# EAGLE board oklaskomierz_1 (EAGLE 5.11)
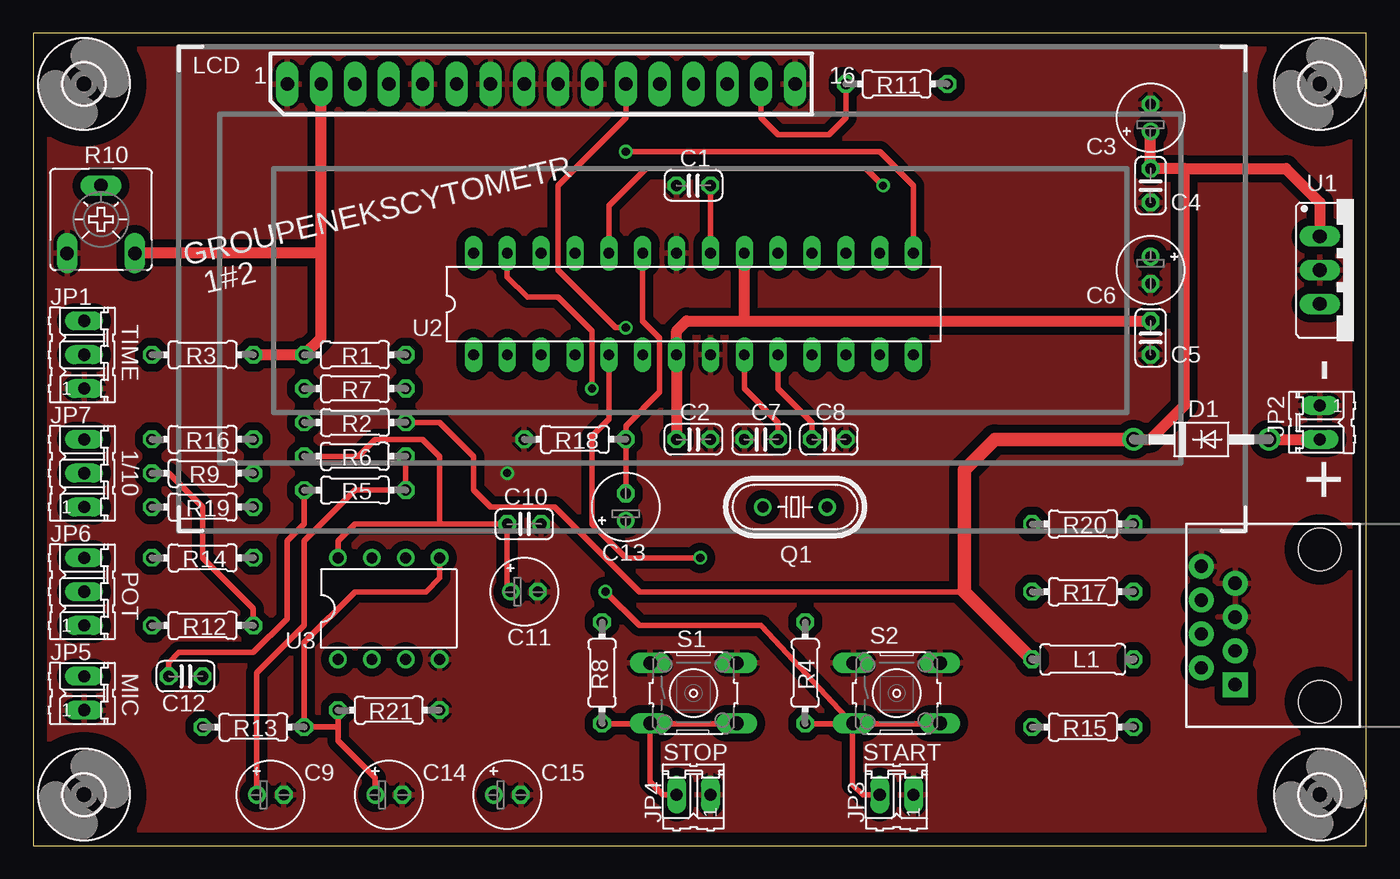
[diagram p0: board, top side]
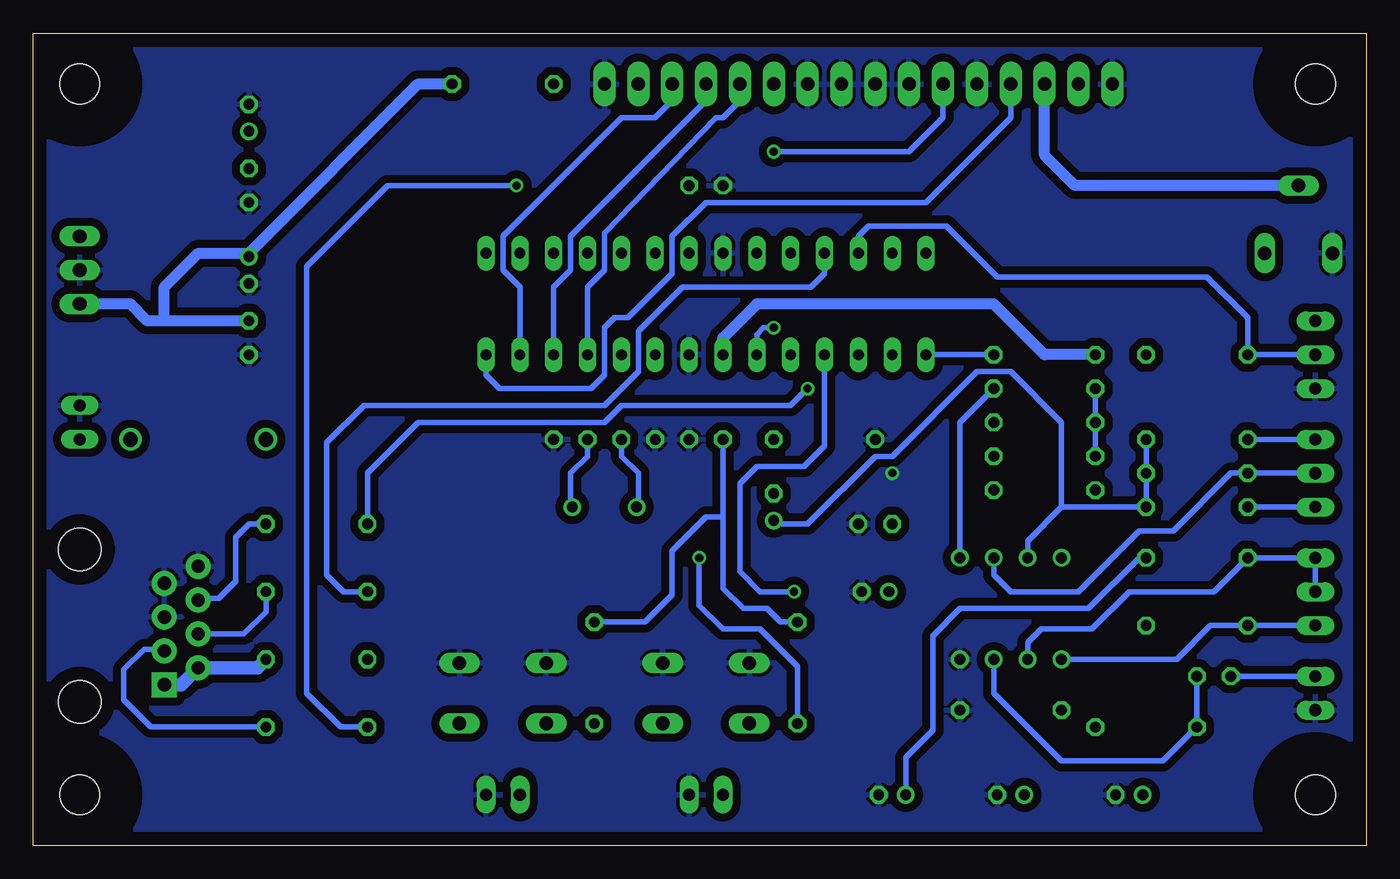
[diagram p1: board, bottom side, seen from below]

Size 100 x 60.95 mm. Coordinates in mm from the lower left corner, seen from the top.
Outline: 0,0 100,0 100,60.95 0,60.95 0,0
Copper layers (1*16): Top 0.035mm / dielectric 1.5mm / Bottom 0.035mm
Design rules "default *": minimum track width 16mil, minimum drill 24mil, track to track 8mil, track to pad 8mil, pad to pad 8mil, via to via 8mil, smd to smd 8mil, copper to edge 40mil, drill to drill 8mil, minimum pad ring 10mil, minimum via ring 8mil, stop-mask expansion 4mil, vias tented up to drill 0mil, thermal gap 10mil

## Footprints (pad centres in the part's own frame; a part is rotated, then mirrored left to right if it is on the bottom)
C025-024X044 = drill 0.813 octagon: 1 -1.27,0; 2 1.27,0
E2-5 = drill 0.813 pad 1.27 round: + -1.016,0 | drill 0.813 pad 1.27 octagon: - 1.016,0
RJ45-8 = drill 1 pad 1.88 square: 1 -4.445,6.35 | drill 1 pad 1.88 round: 2 -3.175,8.89; 3 -1.905,6.35; 4 -0.635,8.89; 5 0.635,6.35; 6 1.905,8.89; 7 3.175,6.35; 8 4.445,8.89 | hole 3.2: -5.715,0; 5.715,0
DO41-10 = drill 1.118 round: A 5.08,0; C -5.08,0
3,0 = hole 3: 0,0
03P = drill 0.914 long: 1 -2.54,0; 2 0,0; 3 2.54,0
02P = drill 0.914 long: 1 -1.27,0; 2 1.27,0
0207/7 = drill 0.813 octagon: 1 -3.81,0; 2 3.81,0
LCD16X2 = drill 1 pad 1.676 long: 1 -15.24,6.35; 2 -12.7,6.35; 3 -10.16,6.35; 4 -7.62,6.35; 5 -5.08,6.35; 6 -2.54,6.35; 7 0,6.35; 8 2.54,6.35; 9 5.08,6.35; 10 7.62,6.35; 11 10.16,6.35; 12 12.7,6.35; 13 15.24,6.35; 14 17.78,6.35; 15 20.32,6.35; 16 22.86,6.35
HC49/S = drill 0.813 round: 1 -2.413,0; 2 2.413,0
0204/7 = drill 0.813 octagon: 1 -3.81,0; 2 3.81,0
CA6V = drill 1.016 long: A -2.54,-2.54; E 2.54,-2.54; S 0,2.54
B3F-10XX = drill 1.016 long: 1 -3.251,2.261; 2 3.251,2.261; 3 -3.251,-2.261; 4 3.251,-2.261
78XXS = drill 1.016 long: GND 0,-2.54; IN -2.54,-2.54; OUT 2.54,-2.54
DIL28-3 = drill 0.813 long: 1 -16.51,-3.81; 2 -13.97,-3.81; 3 -11.43,-3.81; 4 -8.89,-3.81; 5 -6.35,-3.81; 6 -3.81,-3.81; 7 -1.27,-3.81; 8 1.27,-3.81; 9 3.81,-3.81; 10 6.35,-3.81; 11 8.89,-3.81; 12 11.43,-3.81; 13 13.97,-3.81; 14 16.51,-3.81; 15 16.51,3.81; 16 13.97,3.81; 17 11.43,3.81; 18 8.89,3.81; 19 6.35,3.81; 20 3.81,3.81; 21 1.27,3.81; 22 -1.27,3.81; 23 -3.81,3.81; 24 -6.35,3.81; 25 -8.89,3.81; 26 -11.43,3.81; 27 -13.97,3.81; 28 -16.51,3.81
DIL08 = drill 0.813 pad 1.27 round: 1 -3.81,-3.81; 2 -1.27,-3.81; 3 1.27,-3.81; 4 3.81,-3.81; 5 3.81,3.81; 6 1.27,3.81; 7 -1.27,3.81; 8 -3.81,3.81

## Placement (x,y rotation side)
C1  100n  [C025-024X044]  49.53,49.53 180 top
C2  100n  [C025-024X044]  49.53,30.48 0 top
C3  220uF  [E2-5]  83.82,54.61 90 top
C4  100n  [C025-024X044]  83.82,49.53 270 top
C5  100n  [C025-024X044]  83.82,38.1 270 top
C6  100uF  [E2-5]  83.82,43.18 270 top
C7  22pF  [C025-024X044]  54.61,30.48 180 top
C8  22pF  [C025-024X044]  59.69,30.48 0 top
C9  10uF  [E2-5]  17.78,3.81 0 top
C10  100nF  [C025-024X044]  36.83,24.13 0 top
C11  100uF  [E2-5]  36.83,19.05 0 top
C12  100nF  [C025-024X044]  11.43,12.7 0 top
C13  10uF  [E2-5]  44.45,25.4 90 top
C14  100uF  [E2-5]  26.67,3.81 0 top
C15  10uF  [E2-5]  35.56,3.81 0 top
CON1  EXT  [RJ45-8]  96.52,16.51 90 top
D1  1N4007  [DO41-10]  87.63,30.48 0 top
H1  MOUNT-HOLE3.0  [3,0]  96.52,3.81 0 top
H2  MOUNT-HOLE3.0  [3,0]  3.81,3.81 0 top
H3  MOUNT-HOLE3.0  [3,0]  96.52,57.15 0 top
H4  MOUNT-HOLE3.0  [3,0]  3.81,57.15 0 top
JP1  TIME  [03P]  3.81,36.83 90 top
JP2  POW  [02P]  96.52,31.75 270 top
JP3  START  [02P]  64.77,3.81 180 top
JP4  STOP  [02P]  49.53,3.81 180 top
JP5  MIC  [02P]  3.81,11.43 90 top
JP6  POT10k  [03P]  3.81,19.05 90 top
JP7  1/10  [03P]  3.81,27.94 90 top
L1  10uH  [0207/7]  78.74,13.97 0 top
LCD  LCD16X2  [LCD16X2]  34.29,50.8 0 top
Q1  16MHz  [HC49/S]  57.15,25.4 180 top
R1  10k  [0204/7]  24.13,36.83 0 top
R2  100R  [0204/7]  24.13,31.75 180 top
R3  10k  [0204/7]  12.7,36.83 0 top
R4  10k  [0204/7]  57.91,12.95 90 top
R5  2k2  [0204/7]  24.13,26.67 180 top
R6  2k2  [0204/7]  24.13,29.21 0 top
R7  10k  [0204/7]  24.13,34.29 0 top
R8  10k  [0204/7]  42.67,12.95 90 top
R9  22k  [0204/7]  12.7,27.94 0 top
R10  [CA6V]  5.08,46.99 0 top
R11  10R  [0204/7]  64.77,57.15 0 top
R12  2k2  [0204/7]  12.7,16.51 0 top
R13  100k  [0204/7]  16.51,8.89 0 top
R14  1k  [0204/7]  12.7,21.59 0 top
R15  10R  [0204/7]  78.74,8.89 180 top
R16  10k  [0204/7]  12.7,30.48 0 top
R17  10R  [0204/7]  78.74,19.05 180 top
R18  10k  [0204/7]  40.64,30.48 0 top
R19  2k2  [0204/7]  12.7,25.4 0 top
R20  10R  [0204/7]  78.74,24.13 180 top
R21  10k  [0204/7]  26.67,10.16 0 top
S1  [B3F-10XX]  49.53,11.43 0 top
S2  [B3F-10XX]  64.77,11.43 0 top
U1  7805  [78XXS]  99.06,43.18 270 top
U2  MEGA8-P  [DIL28-3]  49.53,40.64 0 top
U3  NE5532N  [DIL08]  26.67,17.78 0 top

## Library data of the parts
C1-C15 L1 R1-R9 R11-R21 = rcl
CON1 = SparkFun
D1 = diode
H1-H4 = holes
JP1-JP7 = con-amp-quick; OC_FARNELL: unknown; OC_NEWARK: unknown
LCD = ds_lib_eagle
Q1 = crystal; OC_FARNELL: 1667008; OC_NEWARK: unknown
R10 = pot
S1 S2 = switch-omron; MPN: B3F-1000; OC_FARNELL: 176432; OC_NEWARK: 36M3542
U1 = v-reg
U2 = atmel; OC_FARNELL: unknown; OC_NEWARK: unknown
U3 = linear

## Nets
+5V: C2.1 C5.1 C6.+ LCD.2 R1.1 R3.2 R4.2 R8.2 R10.E R11.2 U1.OUT U2.7 U2.20
DB4: LCD.11 U2.6
DB5: LCD.12 U2.11
DB6: LCD.13 U2.12
DB7: LCD.14 U2.13
EN: LCD.6 U2.15
GND: C1.2 C2.2 C3.- C4.2 C5.2 C6.- C7.2 C8.2 C9.- C10.2 C11.- C14.- C15.- CON1.5 CON1.7 CON1.8 JP1.1 JP2.1 JP3.1 JP4.1 JP5.1 LCD.1 LCD.5 LCD.7 LCD.8 LCD.9 LCD.10 LCD.16 R10.A R18.1 R21.2 S1.1 S1.2 S2.1 S2.2 U1.GND U2.8 U2.22 U3.4
LCLK: R17.2 U2.25
LDTA: R15.2 U2.24
MIC: C13.- R18.2 U2.23
MICVCC: C10.1 C11.+ R2.2 R6.1 R7.1 U3.8
N$1: D1.A JP2.2
N$2: C12.2 R13.1 U3.3
N$3: C13.+ R9.2 R16.2 R19.2 U3.7
N$4: C15.+ R14.2
N$5: C9.+ R5.1 R6.2
N$6: C12.1 JP5.2 R5.2
N$7: JP6.2 JP6.3 R14.1 U3.2
N$8: JP7.1 R19.1
N$9: CON1.6 R20.1
N$10: JP6.1 R12.1 U3.1
N$11: JP7.2 R9.1 R12.2 U3.6
N$12: C14.+ R7.2 R13.2 R21.1 U3.5
N$13: JP7.3 R16.1
N$15: CON1.4 R17.1
N$16: CON1.3 R15.1
N$17: CON1.1 CON1.2 L1.2
N$18: C1.1 U2.21
N$23: LCD.15 R11.1
N$24: C7.1 Q1.2 U2.9
N$25: C8.1 Q1.1 U2.10
N$26: R1.2 U2.1
N$27: LCD.3 R10.S
RS: LCD.4 U2.14
SERVO: R20.2 U2.27
SW1: JP4.2 R8.1 S1.3 S1.4 U2.5
SW2: JP3.2 R4.1 S2.3 S2.4 U2.4
SWT: JP1.2 R3.1 U2.26
VCC: C3.+ C4.1 D1.C L1.1 R2.1 U1.IN

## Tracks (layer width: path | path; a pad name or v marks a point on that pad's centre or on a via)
+5V
  Top 0.813: C2.1 U2.7 48.26,38.61 49.02,39.37 53.34,39.37 | 53.34,39.37 U2.20 | 53.34,39.37 C5.1 | 21.59,44.45 21.59,38.1 R1.1 R3.2 | 21.59,44.45 LCD.2 | 21.59,44.45 R10.E
  Bottom 0.406: 83.82,44.45 C6.+ | R8.2 43.94,16.76 44.96,17.78 46.74,17.78 48.26,19.3 48.26,24.64 | C2.1 48.26,24.64 | 48.26,24.64 49.53,24.64 52.07,22.1 52.07,18.8 54.1,16.76 R4.2
  Bottom 0.813: C5.1 90.17,39.37 | 90.17,39.37 91.19,39.37 91.44,39.37 92.71,40.64 U1.OUT | 90.17,39.37 90.17,41.91 87.63,44.45 83.82,44.45 71.12,57.15 R11.2 | R1.1 24.13,36.83 27.94,40.64 45.72,40.64 48.26,38.1 U2.7
DB4  (via drill 0.61)
  Top 0.406: v44.45,38.86 43.69,38.86 42.67,39.88 39.37,43.18 39.37,49.53 44.45,54.61 LCD.11
  Bottom 0.406: v44.45,38.86 45.21,38.86 45.72,38.35 U2.6
DB5
  Bottom 0.406: U2.11 58.42,41.91 57.15,43.18 57.15,45.97 48.77,54.61 48.26,54.61 46.99,55.88 LCD.12
DB6
  Bottom 0.406: U2.12 60.96,41.91 59.69,43.18 59.69,45.72 49.53,55.88 LCD.13
DB7
  Bottom 0.406: U2.13 63.5,41.91 64.77,43.18 64.77,45.72 55.88,54.61 53.34,54.61 52.07,55.88 LCD.14
EN  (via drill 0.61)
  Top 0.406: U2.15 66.04,49.53 63.5,52.07 v44.45,52.07
  Bottom 0.406: v44.45,52.07 34.29,52.07 31.75,54.61 LCD.6
GND  (via drill 0.6)
  other vias: 35.56,27.94
  pour Bottom (isolate 0.61): -1.27,62.48 102.36,62.48 101.85,-1.52 -1.52,-1.27
  pour Top (isolate 0.61): -1.02,61.98 -1.27,-1.02 101.85,-1.52 102.11,62.23
LCLK
  Bottom 0.406: U2.25 40.64,42.93 41.66,41.91 43.18,41.91 51.31,41.91 54.61,38.61 54.61,35.56 57.15,33.02 75.18,33.02 77.98,30.23 77.98,20.32 76.71,19.05 R17.2
LDTA  (via drill 0.61)
  Top 0.406: v63.75,49.53 62.48,50.8 45.97,50.8 43.18,48.01 U2.24
  Bottom 0.406: R15.2 76.96,8.89 79.5,11.43 79.5,28.45 79.5,43.43 73.41,49.53 v63.75,49.53
MIC
  Top 0.406: C13.- R18.2 44.45,31.5 46.99,34.04 46.99,38.1 45.72,39.37 U2.23
MICVCC
  Top 0.406: U3.8 22.86,22.86 24.13,24.13 30.48,24.13 | 30.48,24.13 C10.1 35.56,19.05 C11.+ | R6.1 24.38,29.21 25.65,30.48 29.21,30.48 30.48,29.21 30.48,24.13
  Bottom 0.406: R6.1 R2.2 R7.1
N$1
  Top 0.813: D1.A JP2.2
N$2
  Bottom 0.406: C12.2 R13.1 15.24,6.35 22.86,6.35 27.94,11.43 U3.3
N$3
  Bottom 0.406: R16.2 R9.2 R19.2 22.86,25.4 | U3.7 25.4,22.86 22.86,25.4 | 22.86,25.4 22.86,31.75 26.67,35.56 29.21,35.56 35.56,29.21 36.83,29.21 41.91,24.13 44.45,24.13 C13.+
N$4
  Bottom 0.406: R14.2 17.02,21.59 20.83,17.78 30.48,17.78 32.51,15.75 32.51,8.64 34.54,6.6 C15.+ 34.54,3.56
N$5
  Top 0.406: C9.+ 16.76,12.95 20.32,16.51 20.32,22.86 24.13,26.67 R5.1 R6.2
N$6
  Top 0.406: R5.2 20.32,24.13 19.05,22.86 19.05,17.02 16.51,14.48 10.92,14.48 10.16,13.72 C12.1
  Bottom 0.406: JP5.2 C12.1
N$7
  Bottom 0.406: U3.2 25.4,15.24 24.38,16.26 20.57,16.26 17.78,19.05 11.43,19.05 R14.1 JP6.3 JP6.2
N$8
  Bottom 0.406: JP7.1 R19.1
N$9
  Bottom 0.406: R20.1 83.82,24.13 84.84,23.11 84.84,19.81 86.11,18.54 87.5,18.54 CON1.6
N$10
  Bottom 0.406: JP6.1 R12.1 11.68,16.51 14.22,13.97 U3.1
N$11
  Top 0.406: R12.2 16.51,17.78 12.7,21.59 12.7,25.4 10.16,27.94 R9.1
  Bottom 0.406: JP7.2 R9.1 10.16,27.94 14.48,23.62 17.02,23.62 21.59,19.05 26.67,19.05 27.94,20.32 U3.6
N$12
  Top 0.406: 22.86,8.89 R13.2 20.32,15.24 24.13,19.05 29.46,19.05 30.48,20.07 U3.5 | 22.86,8.89 R21.1 | C14.+ 25.65,5.08 22.86,7.87 22.86,8.89
  Bottom 0.406: R7.2 30.48,31.75 U3.5
N$13
  Bottom 0.406: JP7.3 R16.1
N$15
  Bottom 0.406: CON1.4 84.2,15.87 82.55,17.53 R17.1
N$16
  Bottom 0.406: R15.1 91.19,8.89 93.22,10.92 93.22,13.21 91.69,14.73 90.3,14.73 CON1.3
N$17
  Bottom 1.016: CON1.1 88.9,12.06 CON1.2 83.19,13.33 L1.2
N$18
  Top 0.406: U2.21 C1.1
N$23
  Top 0.406: R11.1 60.96,54.61 59.69,53.34 55.88,53.34 54.61,54.61 LCD.15
N$24
  Top 0.406: U2.9 53.34,34.29 55.88,31.75 C7.1
  Bottom 0.406: C7.1 55.88,29.21 54.61,27.94 54.61,25.4 Q1.2
N$25
  Top 0.406: U2.10 55.88,34.29 58.42,31.75 C8.1
  Bottom 0.406: C8.1 58.42,29.21 59.69,27.94 59.69,25.4 Q1.1
N$26
  Bottom 0.406: R1.2 U2.1
N$27
  Bottom 0.813: R10.S 21.84,49.53 24.13,51.82 LCD.3
RS
  Bottom 0.406: U2.14 66.04,35.31 65.02,34.29 63.5,34.29 58.17,34.29 57.15,35.31 57.15,38.86 56.39,39.62 55.37,39.62 52.07,42.93 52.07,45.72 49.53,48.26 33.02,48.26 26.67,54.61 LCD.4
SERVO  (via drill 0.61)
  Top 0.406: U2.27 35.56,42.67 37.08,41.15 39.37,41.15 41.91,38.61 v41.91,34.29
  Bottom 0.406: v41.91,34.29 43.18,33.02 55.88,33.02 57.15,31.75 71.12,31.75 74.93,27.94 R20.2
SW1  (via drill 0.61)
  Top 0.406: R8.1 47.24,9.14 | 42.93,36.83 U2.5 43.18,32 41.91,30.73 41.91,24.13 42.93,23.11 44.45,21.59 v50.04,21.59 | 47.24,9.14 52.32,9.14 S1.4 | 47.24,9.14 S1.3 46.28,4.77 47.24,3.81 JP4.2
  Bottom 0.406: v50.04,21.59 50.04,18.03 48.26,16.26 45.47,16.26 42.67,13.46 R8.1
SW2  (via drill 0.61)
  Top 0.406: v42.93,19.05 45.47,16.51 54.61,16.51 61.47,9.14 | 61.47,9.14 R4.1 | 61.47,9.14 66.55,9.14 S2.4 | 61.47,9.14 S2.3 61.47,9.12 61.47,4.57 62.23,3.81 JP3.2
  Bottom 0.406: U2.4 40.64,29.97 42.16,28.45 45.72,28.45 46.99,27.18 46.99,20.57 45.47,19.05 v42.93,19.05
SWT
  Bottom 0.406: JP1.2 R3.1 8.89,39.62 11.94,42.67 27.69,42.67 31.5,46.48 37.34,46.48 38.1,45.72 U2.26
VCC
  Top 0.406: R2.1 30.48,31.75 33.02,29.21 33.02,26.67 34.29,25.4 39.12,25.4 45.47,19.05 69.85,19.05
  Top 0.813: C3.+ C4.1 86.36,50.8 | U1.IN 96.52,48.26 93.98,50.8 86.36,50.8 | D1.C 83.82,30.48 86.36,33.02 86.36,50.8
  Top 1.016: L1.1 69.85,19.05 69.85,28.19 72.14,30.48 D1.C

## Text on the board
tNames: GROUPENEKSCYTOMETR | 1#2 | TIME | - | 1/10 | + | POT | MIC | STOP | START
